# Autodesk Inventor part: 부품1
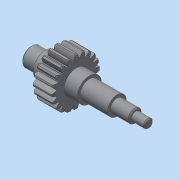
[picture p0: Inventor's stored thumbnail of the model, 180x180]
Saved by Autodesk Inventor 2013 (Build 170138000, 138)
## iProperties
Created: 2019-12
Part Number: 부품1
Material: 일반
Document SubType Name: Modeling
Designer: dgall
Density: 1 g/cm^3
Mass: 35.4008 g
Surface Area: 133.579 cm^2
Volume: 35.4008 cm^3
Author: dgall
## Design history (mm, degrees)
sketch "스케치1"
  geometry: L1 (-9, 0)-(-9, 11); L2 (-9, 11)-(-19, 11); L3 (-19, 11)-(-19, 8.5); L4 (-19, 8.5)-(-32, 8.5); L5 (-32, 8.5)-(-32, 0); L6 (9, 0)-(9, 11); L7 (9, 11)-(21, 11); L8 (21, 11)-(21, 8.5); L9 (21, 8.5)-(46, 8.5); L10 (46, 8.5)-(46, 6); L11 (46, 6)-(63, 6); L12 (63, 6)-(63, 0); L13 (-32, 0)-(-9, 0); L14 (9, 0)-(63, 0); L15 (63, 0)-(63, 4); L16 (63, 4)-(75, 4); L17 (75, 4)-(75, 0); L18 (63, 0)-(75, 0); L19 (63, 0)-(63, 6); 1 further point
  constraints: 38 end point, 6 parallel, 5 perpendicular, 2 collinear, 1 point on line
  dimensions: "d0" = 9 distance of point (0, 0) L1.start; "d1" = 11 distance of L1.start L1.end; "d2" = 10 distance of L1.end L2.end; "d3" = 2.5 distance of L2.end L3.end; "d4" = 13 distance of L3.end L4.end; "d5" = 9 distance of point (0, 0) L6.start; "d6" = 11 distance of L6.start L6.end; "d7" = 12 distance of L6.end L7.end; "d8" = 2.5 distance of L7.end L8.end; "d9" = 25 distance of L8.end L9.end; "d10" = 2.5 distance of L9.end L10.end; "d12" = 6 distance of L11.end L12.end; "d34" = 4 distance of L12.end L15.end; "d35" = 12 distance of L15.end L16.end; "d37" = 6 distance of L12.end L11.end (derived)
revolve "회전1" sketch "스케치1" stored, may be unused: angle "d13" = 90 deg
sketch "스케치2"
  geometry: C1 r 11 at (0, 0) reference; C2 r 17.5 at (0, 0)
  constraints: 1 centre point, 1 coincident
  dimensions: "d14" = 35 diameter of C2
extrude "돌출1" join sketch "스케치2" distance "d15" = 18; taper "d16" = 0 deg
sketch "스케치3"
  geometry: C1 r 17.5 at (0, 0) reference; A1 r 22 centre (0, 0) between (0.75, 21.987) and (-0.75, 21.987); A2 r 17.5 centre (0, 0) between (2.241, 17.356) and (-2.241, 17.356); A3 r 9.388 centre (7.136, 16.892) between (-0.75, 21.987) and (-2.241, 17.356); A4 r 9.388 centre (-7.136, 16.892) between (2.241, 17.356) and (0.75, 21.987)
  constraints: 8 point on circle, 4 centre point, 2 coincident
  dimensions: "d17" = 44 diameter of A1; "d18" = 35 diameter of A2
extrude "돌출2" join sketch "스케치3" stored distance "d20" = 18; taper "d21" = 0 deg
chamfer "모따기1" distance "d22" = 1; stored, may be unused: second distance "d23" = 2, angle "d24" = 45 deg
fillet "모깎기1" dims "d25" = 0.2
node "작업 평면1"
sketch "스케치5"
  geometry: 1 further point
node "작업 평면2"
node "작업 평면3"
sketch "스케치6"
  geometry: L1 (-50.892, -2)-(-56.892, -2); L2 (-50.892, 2)-(-56.892, 2); A1 r 2 centre (-50.892, 0) between (-50.892, -2) and (-50.892, 2); A2 r 2 centre (-56.892, 0) between (-56.892, 2) and (-56.892, -2); 1 further point
  constraints: 4 end point, 4 point on circle, 2 centre point, 2 tangent
extrude "돌출3" cut sketch "스케치6" distance "d43" = 2.5; taper "d44" = 0 deg
chamfer "모따기2" distance "d45" = 1; stored, may be unused: second distance "d46" = 2, angle "d47" = 45 deg
node "솔리드1"
pattern_circular "원형 패턴1" dims "d27" = 360 deg
other parameters: "d29" = 8.5, "d36" = 6, "d38" = 6
